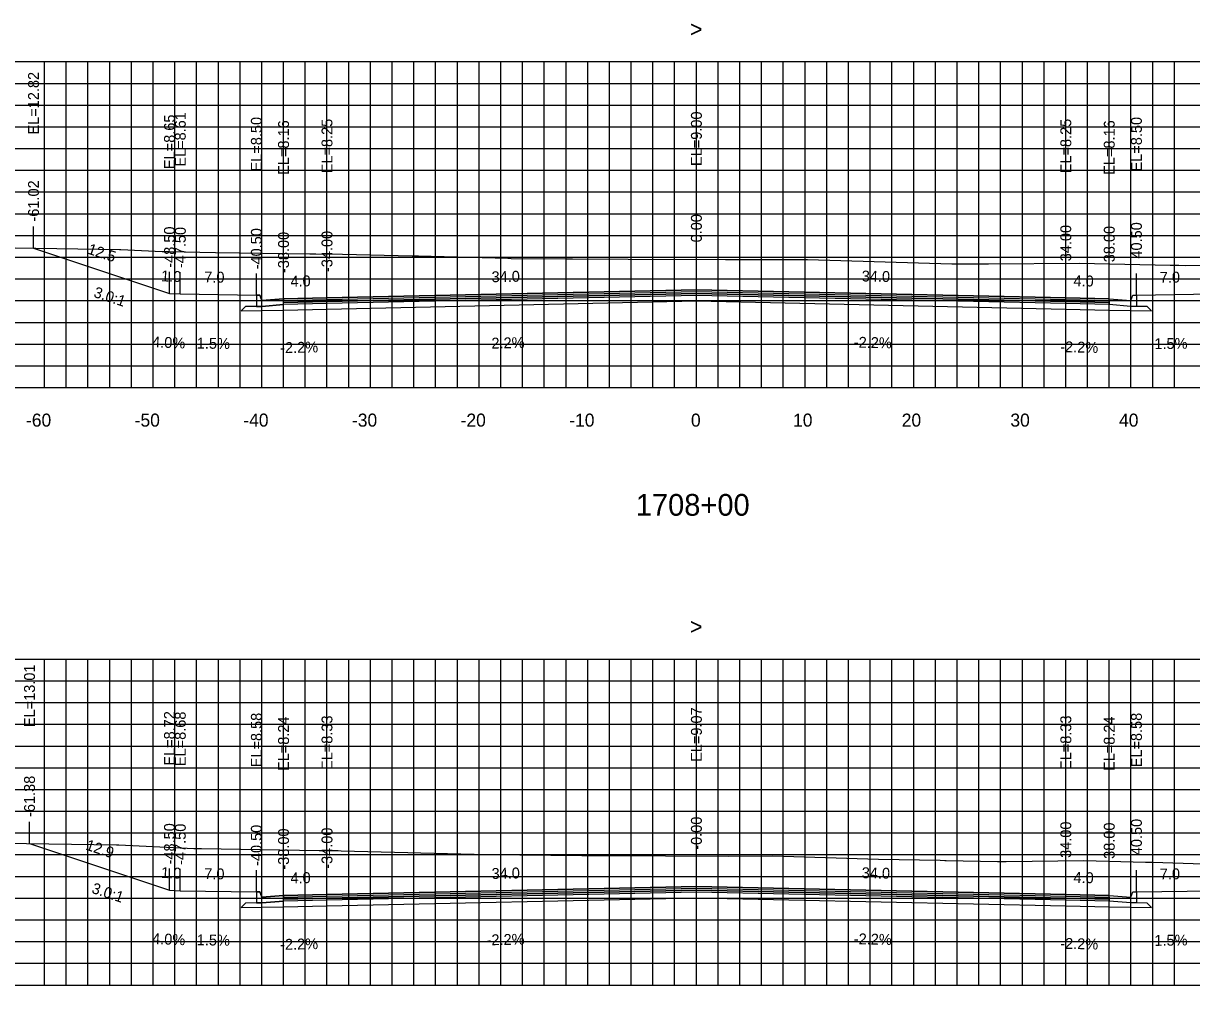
# Model space of a CAD drawing. Extents: x 1797789 to 1803805, y 249066 to 250293.
# Drawn here: x 1803249.1 to 1803356.6, y 250164.4 to 250253 of the extents above; entities that cross this region are included whole.
import ezdxf

# ---------------------------------------------------------------- set-up
doc = ezdxf.new("R2010")
doc.units = 0
for name, color, linetype in [('1', 7, 'Continuous'), ('10', 7, 'Continuous'), ('3', 7, 'Continuous'), ('4', 7, 'Continuous'), ('60', 7, 'Continuous'), ('BASE', 7, 'Continuous'), ('CL-CNST', 7, 'Continuous'), ('Level 62', 7, 'Continuous'), ('LOWER BINDER', 7, 'Continuous'), ('M-ROADS', 7, 'Continuous'), ('UPPER BINDER', 7, 'Continuous'), ('WEARING', 7, 'Continuous')]:
    doc.layers.add(name, color=color, linetype=linetype)

msp = doc.modelspace()

# ---------------------------------------------------------------- linework, layer by layer
for p, q in [((1803249.99, 250232.25), (1803249.99, 250234.25)), ((1803311, 250228.43), (1803311, 250230.43)), ((1803262.5, 250228.08), (1803262.5, 250230.08)), ((1803263.5, 250228.04), (1803263.5, 250230.04)), ((1803270.5, 250227.93), (1803270.5, 250229.93)), ((1803270.5, 250227.93), (1803270.5, 250229.93)), ((1803273, 250227.59), (1803273, 250229.59)), ((1803277, 250227.68), (1803277, 250229.68)), ((1803345, 250227.68), (1803345, 250229.68)), ((1803349, 250227.59), (1803349, 250229.59)), ((1803351.5, 250227.93), (1803351.5, 250229.93)), ((1803351.5, 250227.93), (1803351.5, 250229.93)), ((1803249.62, 250177.45), (1803249.62, 250179.45)), ((1803311, 250173.5), (1803311, 250175.5)), ((1803262.5, 250173.15), (1803262.5, 250175.15)), ((1803263.5, 250173.11), (1803263.5, 250175.11)), ((1803270.5, 250173.01), (1803270.5, 250175.01)), ((1803270.5, 250173.01), (1803270.5, 250175.01)), ((1803273, 250172.67), (1803273, 250174.67)), ((1803277, 250172.76), (1803277, 250174.76)), ((1803345, 250172.76), (1803345, 250174.76)), ((1803349, 250172.67), (1803349, 250174.67)), ((1803351.5, 250173.01), (1803351.5, 250175.01)), ((1803351.5, 250173.01), (1803351.5, 250175.01))]:
    msp.add_line(p, q)
for points in [[(1803273, 250227.59), (1803271, 250227.43), (1803270.83, 250227.93), (1803270.5, 250227.93), (1803270.5, 250226.9), (1803271, 250226.9), (1803273, 250227.06)], [(1803349, 250227.59), (1803351, 250227.43), (1803351.17, 250227.93), (1803351.5, 250227.93), (1803351.5, 250226.9), (1803351, 250226.9), (1803349, 250227.06)], [(1803273, 250172.67), (1803271, 250172.51), (1803270.83, 250173.01), (1803270.5, 250173.01), (1803270.5, 250171.98), (1803271, 250171.98), (1803273, 250172.14)], [(1803349, 250172.67), (1803351, 250172.51), (1803351.17, 250173.01), (1803351.5, 250173.01), (1803351.5, 250171.98), (1803351, 250171.98), (1803349, 250172.14)]]:
    msp.add_lwpolyline(points, close=True)
at = {"layer": '60'}
for p, q in [((1803161, 250219.43), (1803461, 250219.43)), ((1803251, 250219.37), (1803251, 250219.43)), ((1803261, 250219.37), (1803261, 250219.43)), ((1803271, 250219.37), (1803271, 250219.43)), ((1803281, 250219.37), (1803281, 250219.43)), ((1803291, 250219.37), (1803291, 250219.43)), ((1803301, 250219.37), (1803301, 250219.43)), ((1803311, 250219.37), (1803311, 250219.43)), ((1803321, 250219.37), (1803321, 250219.43)), ((1803331, 250219.37), (1803331, 250219.43)), ((1803341, 250219.37), (1803341, 250219.43)), ((1803351, 250219.37), (1803351, 250219.43)), ((1803161, 250164.43), (1803461, 250164.43)), ((1803251, 250164.37), (1803251, 250164.43)), ((1803261, 250164.37), (1803261, 250164.43)), ((1803271, 250164.37), (1803271, 250164.43)), ((1803281, 250164.37), (1803281, 250164.43)), ((1803291, 250164.37), (1803291, 250164.43)), ((1803301, 250164.37), (1803301, 250164.43)), ((1803311, 250164.37), (1803311, 250164.43)), ((1803321, 250164.37), (1803321, 250164.43)), ((1803331, 250164.37), (1803331, 250164.43)), ((1803341, 250164.37), (1803341, 250164.43)), ((1803351, 250164.37), (1803351, 250164.43))]:
    msp.add_line(p, q, dxfattribs=at)
at = {"layer": 'BASE'}
for points in [[(1803349, 250226.56), (1803352.9, 250226.48), (1803352.5, 250226.88), (1803351.5, 250226.9), (1803351, 250226.9), (1803349, 250227.06), (1803345, 250227.15), (1803311, 250227.9), (1803277, 250227.15), (1803273, 250227.06), (1803271, 250226.9), (1803270.5, 250226.9), (1803269.5, 250226.88), (1803269.1, 250226.48), (1803273, 250226.56), (1803277, 250226.65), (1803311, 250227.4), (1803345, 250226.65)], [(1803349, 250171.64), (1803352.9, 250171.55), (1803352.5, 250171.96), (1803351.5, 250171.98), (1803351, 250171.98), (1803349, 250172.14), (1803345, 250172.23), (1803311, 250172.97), (1803277, 250172.23), (1803273, 250172.14), (1803271, 250171.98), (1803270.5, 250171.98), (1803269.5, 250171.96), (1803269.1, 250171.55), (1803273, 250171.64), (1803277, 250171.73), (1803311, 250172.47), (1803345, 250171.73)]]:
    msp.add_lwpolyline(points, close=True, dxfattribs=at)
at = {"layer": 'CL-CNST'}
for points in [[(1803249.99, 250232.25), (1803262.5, 250228.08), (1803263.5, 250228.04), (1803270.5, 250227.93), (1803270.5, 250227.93), (1803270.83, 250227.93), (1803271, 250227.43), (1803273, 250227.59), (1803277, 250227.68), (1803311, 250228.43), (1803345, 250227.68), (1803349, 250227.59), (1803351, 250227.43), (1803351.17, 250227.93), (1803351.5, 250227.93), (1803351.5, 250227.93), (1803358.5, 250228.04), (1803359.5, 250228.08), (1803461, 250228.34)], [(1803249.62, 250177.45), (1803262.5, 250173.15), (1803263.5, 250173.11), (1803270.5, 250173.01), (1803270.5, 250173.01), (1803270.83, 250173.01), (1803271, 250172.51), (1803273, 250172.67), (1803277, 250172.76), (1803311, 250173.5), (1803345, 250172.76), (1803349, 250172.67), (1803351, 250172.51), (1803351.17, 250173.01), (1803351.5, 250173.01), (1803351.5, 250173.01), (1803358.5, 250173.11), (1803359.5, 250173.15), (1803461, 250173.41)]]:
    msp.add_lwpolyline(points, dxfattribs=at)
at = {"layer": 'Level 62'}
for p, q in [((1803161, 250249.43), (1803461, 250249.43)), ((1803251, 250219.43), (1803251, 250249.43)), ((1803253, 250219.43), (1803253, 250249.43)), ((1803255, 250219.43), (1803255, 250249.43)), ((1803257, 250219.43), (1803257, 250249.43)), ((1803259, 250219.43), (1803259, 250249.43)), ((1803261, 250219.43), (1803261, 250249.43)), ((1803263, 250219.43), (1803263, 250249.43)), ((1803265, 250219.43), (1803265, 250249.43)), ((1803267, 250219.43), (1803267, 250249.43)), ((1803269, 250219.43), (1803269, 250249.43)), ((1803271, 250219.43), (1803271, 250249.43)), ((1803273, 250219.43), (1803273, 250249.43)), ((1803275, 250219.43), (1803275, 250249.43)), ((1803277, 250219.43), (1803277, 250249.43)), ((1803279, 250219.43), (1803279, 250249.43)), ((1803281, 250219.43), (1803281, 250249.43)), ((1803283, 250219.43), (1803283, 250249.43)), ((1803285, 250219.43), (1803285, 250249.43)), ((1803287, 250219.43), (1803287, 250249.43)), ((1803289, 250219.43), (1803289, 250249.43)), ((1803291, 250219.43), (1803291, 250249.43)), ((1803293, 250219.43), (1803293, 250249.43)), ((1803295, 250219.43), (1803295, 250249.43)), ((1803297, 250219.43), (1803297, 250249.43)), ((1803299, 250219.43), (1803299, 250249.43)), ((1803301, 250219.43), (1803301, 250249.43)), ((1803303, 250219.43), (1803303, 250249.43)), ((1803305, 250219.43), (1803305, 250249.43)), ((1803307, 250219.43), (1803307, 250249.43)), ((1803309, 250219.43), (1803309, 250249.43)), ((1803311, 250219.43), (1803311, 250249.43)), ((1803313, 250219.43), (1803313, 250249.43)), ((1803315, 250219.43), (1803315, 250249.43)), ((1803317, 250219.43), (1803317, 250249.43)), ((1803319, 250219.43), (1803319, 250249.43)), ((1803321, 250219.43), (1803321, 250249.43)), ((1803323, 250219.43), (1803323, 250249.43)), ((1803325, 250219.43), (1803325, 250249.43)), ((1803327, 250219.43), (1803327, 250249.43)), ((1803329, 250219.43), (1803329, 250249.43)), ((1803331, 250219.43), (1803331, 250249.43)), ((1803333, 250219.43), (1803333, 250249.43)), ((1803335, 250219.43), (1803335, 250249.43)), ((1803337, 250219.43), (1803337, 250249.43)), ((1803339, 250219.43), (1803339, 250249.43)), ((1803341, 250219.43), (1803341, 250249.43)), ((1803343, 250219.43), (1803343, 250249.43)), ((1803345, 250219.43), (1803345, 250249.43)), ((1803347, 250219.43), (1803347, 250249.43)), ((1803349, 250219.43), (1803349, 250249.43)), ((1803351, 250219.43), (1803351, 250249.43)), ((1803353, 250219.43), (1803353, 250249.43)), ((1803355, 250219.43), (1803355, 250249.43)), ((1803161, 250247.43), (1803461, 250247.43)), ((1803161, 250245.43), (1803461, 250245.43)), ((1803161, 250243.43), (1803461, 250243.43)), ((1803161, 250241.43), (1803461, 250241.43)), ((1803161, 250239.43), (1803461, 250239.43)), ((1803161, 250237.43), (1803461, 250237.43)), ((1803161, 250235.43), (1803461, 250235.43)), ((1803161, 250233.43), (1803461, 250233.43)), ((1803161, 250231.43), (1803461, 250231.43)), ((1803161, 250229.43), (1803461, 250229.43)), ((1803161, 250227.43), (1803461, 250227.43)), ((1803161, 250225.43), (1803461, 250225.43)), ((1803161, 250223.43), (1803461, 250223.43)), ((1803161, 250221.43), (1803461, 250221.43)), ((1803161, 250219.43), (1803461, 250219.43)), ((1803161, 250194.43), (1803461, 250194.43)), ((1803251, 250164.43), (1803251, 250194.43)), ((1803253, 250164.43), (1803253, 250194.43)), ((1803255, 250164.43), (1803255, 250194.43)), ((1803257, 250164.43), (1803257, 250194.43)), ((1803259, 250164.43), (1803259, 250194.43)), ((1803261, 250164.43), (1803261, 250194.43)), ((1803263, 250164.43), (1803263, 250194.43)), ((1803265, 250164.43), (1803265, 250194.43)), ((1803267, 250164.43), (1803267, 250194.43)), ((1803269, 250164.43), (1803269, 250194.43)), ((1803271, 250164.43), (1803271, 250194.43)), ((1803273, 250164.43), (1803273, 250194.43)), ((1803275, 250164.43), (1803275, 250194.43)), ((1803277, 250164.43), (1803277, 250194.43)), ((1803279, 250164.43), (1803279, 250194.43)), ((1803281, 250164.43), (1803281, 250194.43)), ((1803283, 250164.43), (1803283, 250194.43)), ((1803285, 250164.43), (1803285, 250194.43)), ((1803287, 250164.43), (1803287, 250194.43)), ((1803289, 250164.43), (1803289, 250194.43)), ((1803291, 250164.43), (1803291, 250194.43)), ((1803293, 250164.43), (1803293, 250194.43)), ((1803295, 250164.43), (1803295, 250194.43)), ((1803297, 250164.43), (1803297, 250194.43)), ((1803299, 250164.43), (1803299, 250194.43)), ((1803301, 250164.43), (1803301, 250194.43)), ((1803303, 250164.43), (1803303, 250194.43)), ((1803305, 250164.43), (1803305, 250194.43)), ((1803307, 250164.43), (1803307, 250194.43)), ((1803309, 250164.43), (1803309, 250194.43)), ((1803311, 250164.43), (1803311, 250194.43)), ((1803313, 250164.43), (1803313, 250194.43)), ((1803315, 250164.43), (1803315, 250194.43)), ((1803317, 250164.43), (1803317, 250194.43)), ((1803319, 250164.43), (1803319, 250194.43)), ((1803321, 250164.43), (1803321, 250194.43)), ((1803323, 250164.43), (1803323, 250194.43)), ((1803325, 250164.43), (1803325, 250194.43)), ((1803327, 250164.43), (1803327, 250194.43)), ((1803329, 250164.43), (1803329, 250194.43)), ((1803331, 250164.43), (1803331, 250194.43)), ((1803333, 250164.43), (1803333, 250194.43)), ((1803335, 250164.43), (1803335, 250194.43)), ((1803337, 250164.43), (1803337, 250194.43)), ((1803339, 250164.43), (1803339, 250194.43)), ((1803341, 250164.43), (1803341, 250194.43)), ((1803343, 250164.43), (1803343, 250194.43)), ((1803345, 250164.43), (1803345, 250194.43)), ((1803347, 250164.43), (1803347, 250194.43)), ((1803349, 250164.43), (1803349, 250194.43)), ((1803351, 250164.43), (1803351, 250194.43)), ((1803353, 250164.43), (1803353, 250194.43)), ((1803355, 250164.43), (1803355, 250194.43)), ((1803161, 250192.43), (1803461, 250192.43)), ((1803161, 250190.43), (1803461, 250190.43)), ((1803161, 250188.43), (1803461, 250188.43)), ((1803161, 250186.43), (1803461, 250186.43)), ((1803161, 250184.43), (1803461, 250184.43)), ((1803161, 250182.43), (1803461, 250182.43)), ((1803161, 250180.43), (1803461, 250180.43)), ((1803161, 250178.43), (1803461, 250178.43)), ((1803161, 250176.43), (1803461, 250176.43)), ((1803161, 250174.43), (1803461, 250174.43)), ((1803161, 250172.43), (1803461, 250172.43)), ((1803161, 250170.43), (1803461, 250170.43)), ((1803161, 250168.43), (1803461, 250168.43)), ((1803161, 250166.43), (1803461, 250166.43)), ((1803161, 250164.43), (1803461, 250164.43))]:
    msp.add_line(p, q, dxfattribs=at)
at = {"layer": 'LOWER BINDER'}
for points in [[(1803273, 250227.06), (1803273, 250227.25), (1803277, 250227.34), (1803311, 250228.09), (1803345, 250227.34), (1803349, 250227.25), (1803349, 250227.06), (1803345, 250227.15), (1803311, 250227.9), (1803277, 250227.15)], [(1803273, 250172.14), (1803273, 250172.33), (1803277, 250172.42), (1803311, 250173.16), (1803345, 250172.42), (1803349, 250172.33), (1803349, 250172.14), (1803345, 250172.23), (1803311, 250172.97), (1803277, 250172.23)]]:
    msp.add_lwpolyline(points, close=True, dxfattribs=at)
at = {"layer": 'M-ROADS'}
for points in [[(1803242.49, 250232.37), (1803257.91, 250232.13), (1803258.02, 250232.13), (1803261.83, 250231.96), (1803262.1, 250231.96), (1803262.44, 250231.96), (1803266.75, 250231.87), (1803275.42, 250231.73), (1803275.81, 250231.73), (1803275.96, 250231.73), (1803278.43, 250231.72), (1803284.84, 250231.56), (1803285.43, 250231.55), (1803293.66, 250231.33), (1803293.94, 250231.32), (1803299.09, 250231.27), (1803299.36, 250231.27), (1803299.6, 250231.28), (1803304.73, 250231.24), (1803313.69, 250231.21), (1803321.24, 250231.23), (1803334.51, 250230.82), (1803335.01, 250230.82), (1803335.07, 250230.81), (1803337.11, 250230.81), (1803337.24, 250230.81), (1803337.9, 250230.82), (1803346.26, 250230.89), (1803354.6, 250230.69), (1803354.67, 250230.69), (1803355.41, 250230.68), (1803356.04, 250230.67), (1803358.32, 250230.69)], [(1803247.25, 250177.48), (1803257.62, 250177.32), (1803257.83, 250177.33), (1803264.74, 250177.01), (1803264.86, 250177), (1803265.15, 250177), (1803265.2, 250177), (1803265.46, 250177), (1803276.28, 250176.82), (1803277.42, 250176.8), (1803277.45, 250176.8), (1803277.78, 250176.8), (1803278.02, 250176.8), (1803278.32, 250176.79), (1803291.76, 250176.44), (1803291.91, 250176.43), (1803300.47, 250176.35), (1803300.91, 250176.35), (1803300.97, 250176.35), (1803302.32, 250176.34), (1803313.98, 250176.3), (1803318.02, 250176.31), (1803327.77, 250176.01), (1803333.43, 250175.92), (1803333.88, 250175.9), (1803333.99, 250175.9), (1803338.7, 250175.81), (1803339.26, 250175.81), (1803339.51, 250175.81), (1803346.67, 250175.88), (1803352.34, 250175.73), (1803352.77, 250175.73), (1803353, 250175.73), (1803357.64, 250175.59)]]:
    msp.add_lwpolyline(points, dxfattribs=at)
at = {"layer": 'UPPER BINDER'}
for points in [[(1803311, 250228.09), (1803277, 250227.34), (1803273, 250227.25), (1803273, 250227.44), (1803277, 250227.53), (1803311, 250228.28), (1803345, 250227.53), (1803349, 250227.44), (1803349, 250227.06), (1803349, 250227.25), (1803345, 250227.34)], [(1803311, 250173.16), (1803277, 250172.42), (1803273, 250172.33), (1803273, 250172.52), (1803277, 250172.61), (1803311, 250173.35), (1803345, 250172.61), (1803349, 250172.52), (1803349, 250172.14), (1803349, 250172.33), (1803345, 250172.42)]]:
    msp.add_lwpolyline(points, close=True, dxfattribs=at)
at = {"layer": 'WEARING'}
for points in [[(1803349, 250227.44), (1803349, 250227.59), (1803345, 250227.68), (1803311, 250228.43), (1803277, 250227.68), (1803273, 250227.59), (1803273, 250227.44), (1803277, 250227.53), (1803311, 250228.28), (1803345, 250227.53)], [(1803349, 250172.52), (1803349, 250172.67), (1803345, 250172.76), (1803311, 250173.5), (1803277, 250172.76), (1803273, 250172.67), (1803273, 250172.52), (1803277, 250172.61), (1803311, 250173.35), (1803345, 250172.61)]]:
    msp.add_lwpolyline(points, close=True, dxfattribs=at)

# ---------------------------------------------------------------- texts
for p in [(1803255.45, 250227.79), (1803255.27, 250172.93)]:
    msp.add_text('3.0:1', height=1, rotation=341.5651).set_placement(p)
at = {"layer": '1'}
msp.add_text('1708+00', height=2, dxfattribs=at).set_placement((1803305.42, 250207.63))
at = {"layer": '10'}
for s, p in [('-60', (1803249.3, 250215.83)), ('-50', (1803259.3, 250215.83)), ('-40', (1803269.3, 250215.83)), ('-30', (1803279.3, 250215.83)), ('-20', (1803289.3, 250215.83)), ('-10', (1803299.3, 250215.83)), ('0', (1803310.5, 250215.83)), ('10', (1803319.9, 250215.83)), ('20', (1803329.9, 250215.83)), ('30', (1803339.9, 250215.83)), ('40', (1803349.9, 250215.83))]:
    msp.add_text(s, height=1.2, dxfattribs=at).set_placement(p)
at = {"layer": '3'}
for s, p in [('EL=12.82', (1803250.49, 250242.72)), ('EL=8.65', (1803263, 250239.54)), ('EL=8.61', (1803264, 250239.76)), ('EL=8.50', (1803271, 250239.32)), ('EL=8.50', (1803271, 250239.32)), ('EL=9.00', (1803311.5, 250239.82)), ('EL=8.50', (1803352, 250239.32)), ('EL=8.50', (1803352, 250239.32)), ('EL=8.16', (1803273.5, 250239.01)), ('EL=8.25', (1803277.5, 250239.15)), ('EL=8.25', (1803345.5, 250239.15)), ('EL=8.16', (1803349.5, 250239.01)), ('-61.02', (1803250.49, 250234.71)), ('0.00', (1803311.5, 250232.79)), ('40.50', (1803352, 250231.3)), ('40.50', (1803352, 250231.3)), ('-48.50', (1803263, 250230.46)), ('-47.50', (1803264, 250230.42)), ('-40.50', (1803271, 250230.31)), ('-40.50', (1803271, 250230.31)), ('-38.00', (1803273.5, 250229.97)), ('-34.00', (1803277.5, 250230.06)), ('34.00', (1803345.5, 250231.05)), ('38.00', (1803349.5, 250230.96)), ('EL=13.01', (1803250.12, 250188.17)), ('EL=8.72', (1803263, 250184.62)), ('EL=8.68', (1803264, 250184.58)), ('EL=8.58', (1803271, 250184.47)), ('EL=8.58', (1803271, 250184.47)), ('EL=9.07', (1803311.5, 250184.97)), ('EL=8.58', (1803352, 250184.47)), ('EL=8.58', (1803352, 250184.47)), ('EL=8.24', (1803273.5, 250184.13)), ('EL=8.33', (1803277.5, 250184.22)), ('EL=8.33', (1803345.5, 250184.22)), ('EL=8.24', (1803349.5, 250184.13)), ('-61.38', (1803250.12, 250179.9)), ('-0.00', (1803311.5, 250176.88)), ('40.50', (1803352, 250176.38)), ('40.50', (1803352, 250176.38)), ('-48.50', (1803263, 250175.53)), ('-47.50', (1803264, 250175.49)), ('-40.50', (1803271, 250175.39)), ('-40.50', (1803271, 250175.39)), ('-38.00', (1803273.5, 250175.05)), ('-34.00', (1803277.5, 250175.13)), ('34.00', (1803345.5, 250176.13)), ('38.00', (1803349.5, 250176.04))]:
    msp.add_text(s, height=1, rotation=90, dxfattribs=at).set_placement(p)
at = {"layer": '4'}
for s, rotation, p in [('12.5', 341.5651, (1803254.9, 250231.77)), ('1.0', 357.7094, (1803261.72, 250229.21)), ('34.0', 1.2603, (1803292.16, 250229.12)), ('34.0', 358.7397, (1803326.21, 250229.2)), ('7.0', 359.1406, (1803265.7, 250229.11)), ('4.0', 1.2603, (1803273.65, 250228.71)), ('4.0', 358.7397, (1803345.7, 250228.77)), ('7.0', 0.8594, (1803353.66, 250229.07)), ('4.0%', 357.7094, (1803260.89, 250223.14)), ('1.5%', 359.1406, (1803265.01, 250223.02)), ('-2.2%', 1.2603, (1803291.7, 250223)), ('-2.2%', 358.7397, (1803325.48, 250223.11)), ('-2.2%', 358.7397, (1803344.48, 250222.69)), ('1.5%', 0.8594, (1803353.16, 250222.96)), ('-2.2%', 1.2603, (1803272.7, 250222.59)), ('12.9', 341.5651, (1803254.72, 250176.91)), ('1.0', 357.7094, (1803261.72, 250174.29)), ('7.0', 359.1406, (1803265.7, 250174.18)), ('4.0', 1.2603, (1803273.65, 250173.78)), ('34.0', 1.2603, (1803292.16, 250174.19)), ('34.0', 358.7397, (1803326.21, 250174.27)), ('4.0', 358.7397, (1803345.7, 250173.84)), ('7.0', 0.8594, (1803353.66, 250174.14)), ('4.0%', 357.7094, (1803260.89, 250168.21)), ('1.5%', 359.1406, (1803265.01, 250168.09)), ('-2.2%', 1.2603, (1803291.7, 250168.08)), ('-2.2%', 358.7397, (1803325.48, 250168.19)), ('1.5%', 0.8594, (1803353.16, 250168.03)), ('-2.2%', 1.2603, (1803272.7, 250167.66)), ('-2.2%', 358.7397, (1803344.48, 250167.77))]:
    msp.add_text(s, height=1, rotation=rotation, dxfattribs=at).set_placement(p)
at = {"layer": '60'}
for p in [(1803310.39, 250251.68), (1803310.39, 250196.68)]:
    msp.add_text('>', height=1.5, dxfattribs=at).set_placement(p)

doc.saveas('drawing.dxf')
